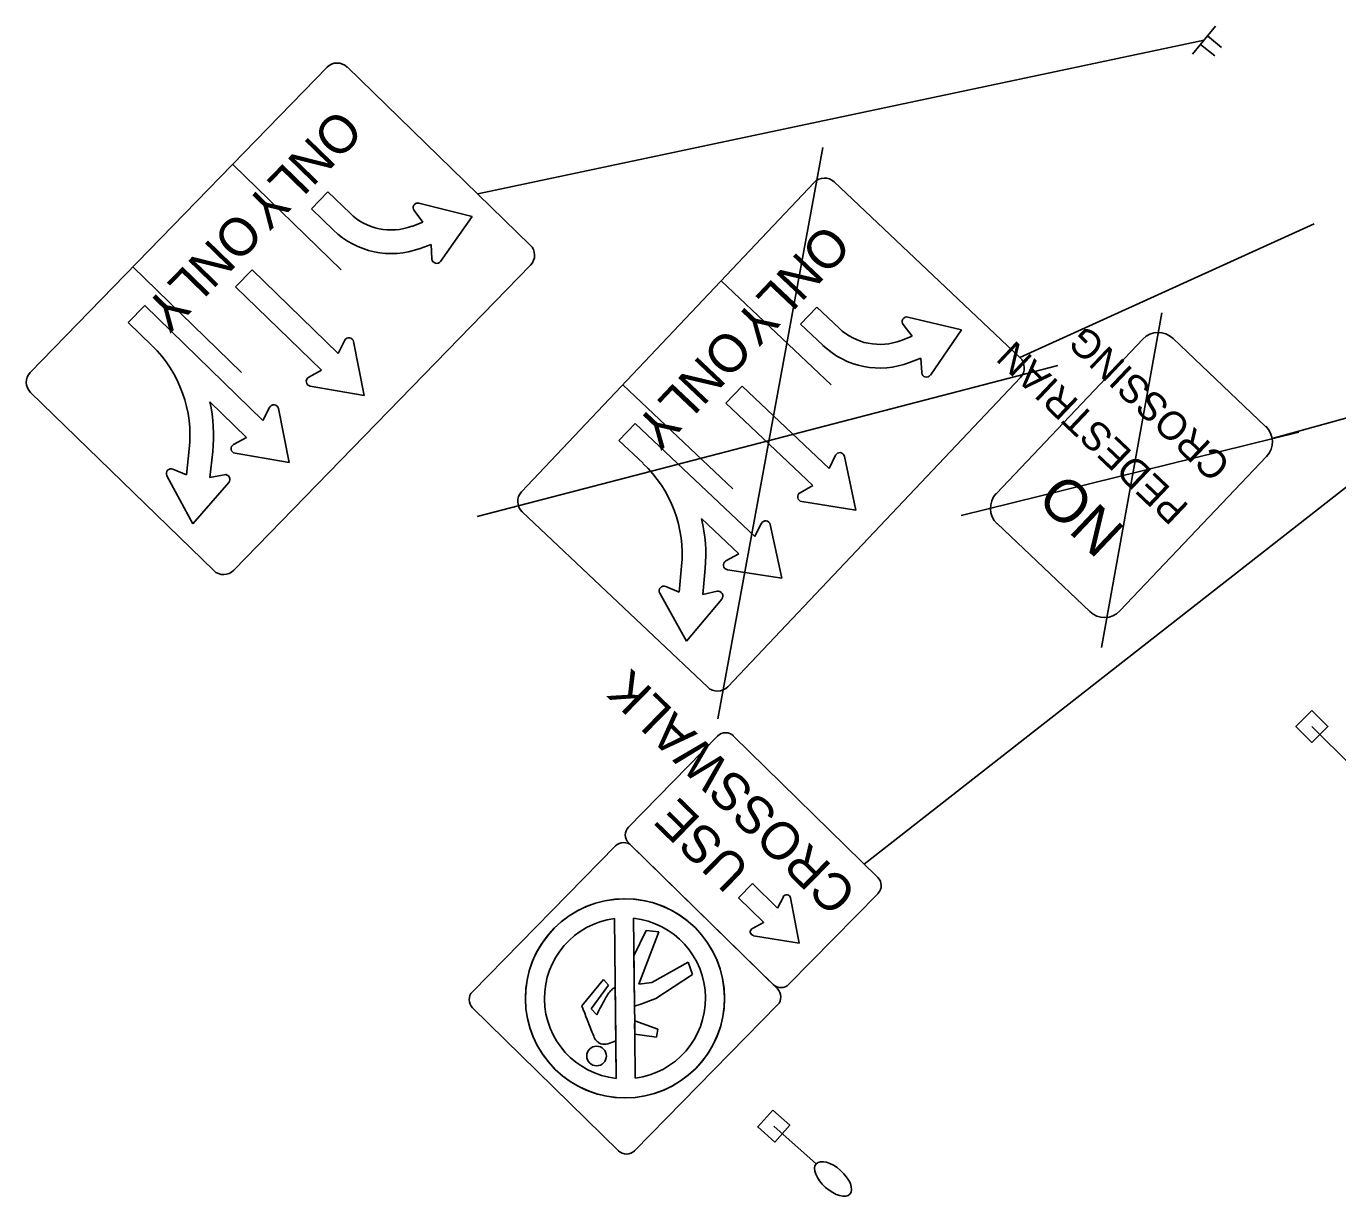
# Model space of a CAD drawing. Extents: x 1481212 to 1485683, y 378085 to 388655.
# Drawn here: x 1481273.4 to 1481389, y 378146.6 to 378249.9 of the extents above; entities that cross this region are included whole.
import ezdxf

# ---------------------------------------------------------------- set-up
doc = ezdxf.new("R2010")
doc.units = 0
for name, color, linetype in [('LT_X_Luminaires', 7, 'Continuous'), ('RW_X_CL_100_Curve_Data', 7, 'Continuous'), ('SC_Scratch15', 7, 'Continuous'), ('SC_Scratch8', 7, 'Continuous'), ('SN_P_Signs', 7, 'Continuous')]:
    doc.layers.add(name, color=color, linetype=linetype)

msp = doc.modelspace()

# ---------------------------------------------------------------- linework, layer by layer
at = {"layer": 'LT_X_Luminaires'}
for p, q in [((1481386.69, 378188.18), (1481390.23, 378184.64)), ((1481339.29, 378152.97), (1481343.02, 378149.64))]:
    msp.add_line(p, q, dxfattribs=at)
for points in [[(1481386.69, 378189.59), (1481388.1, 378188.18), (1481386.69, 378186.76), (1481385.27, 378188.18)], [(1481339.21, 378154.38), (1481340.7, 378153.05), (1481339.37, 378151.56), (1481337.88, 378152.89)]]:
    msp.add_lwpolyline(points, close=True, dxfattribs=at)
msp.add_ellipse((1481344.51, 378148.31), major_axis=(1.49, -1.33), ratio=0.5, dxfattribs=at)
at = {"layer": 'RW_X_CL_100_Curve_Data'}
for p, q in [((1481360.96, 378220.68), (1481386.88, 378232.45)), ((1481344.34, 378218.27), (1481334.65, 378227.43)), ((1481341.65, 378223.61), (1481343.08, 378225.12)), ((1481343.08, 378225.12), (1481345.04, 378223.26)), ((1481351.1, 378224.24), (1481355.81, 378223.12)), ((1481343.61, 378221.75), (1481341.65, 378223.61)), ((1481351.48, 378222.56), (1481350.68, 378223.57)), ((1481355.81, 378223.12), (1481353.08, 378219.13)), ((1481350.5, 378222.18), (1481351.48, 378222.56)), ((1481352.23, 378220.62), (1481351.25, 378220.24)), ((1481352.32, 378219.34), (1481352.23, 378220.62)), ((1481383.18, 378213.53), (1481401.74, 378218.69)), ((1481335.68, 378209.11), (1481325.99, 378218.27)), ((1481336.49, 378218.16), (1481335.06, 378216.64)), ((1481344.16, 378210.9), (1481336.49, 378218.16)), ((1481335.06, 378216.64), (1481342.73, 378209.39)), ((1481327.08, 378214.87), (1481325.65, 378213.36)), ((1481337.63, 378204.9), (1481327.08, 378214.87)), ((1481325.65, 378213.36), (1481327.77, 378211.36)), ((1481344.73, 378212.06), (1481344.16, 378210.9)), ((1481346.52, 378207.24), (1481345.51, 378211.96)), ((1481342.73, 378209.39), (1481341.61, 378208.76)), ((1481341.75, 378207.98), (1481346.52, 378207.24)), ((1481332.92, 378206.48), (1481336.2, 378203.38)), ((1481338.19, 378206.06), (1481337.63, 378204.9)), ((1481339.99, 378201.23), (1481338.97, 378205.96)), ((1481336.2, 378203.38), (1481335.07, 378202.76)), ((1481331.17, 378202.29), (1481330.96, 378200.01)), ((1481333.03, 378199.81), (1481333.25, 378202.09)), ((1481335.21, 378201.98), (1481339.99, 378201.23)), ((1481329.24, 378199.92), (1481331.59, 378195.69)), ((1481330.96, 378200.01), (1481329.77, 378200.5)), ((1481334.29, 378200.08), (1481333.03, 378199.81)), ((1481331.59, 378195.69), (1481334.7, 378199.4))]:
    msp.add_line(p, q, dxfattribs=at)
for points in [[(1481342.84, 378236.09), (1481317.08, 378208.85)], [(1481360.96, 378220.68), (1481344.61, 378236.14)], [(1481371.8, 378222.29), (1481358.89, 378208.69)], [(1481382.61, 378214.61), (1481374.45, 378222.36)], [(1481335.24, 378191.67), (1481361.01, 378218.92)], [(1481369.77, 378198.36), (1481382.68, 378211.96)], [(1481317.13, 378207.08), (1481333.48, 378191.62)], [(1481358.96, 378206.04), (1481367.12, 378198.29)]]:
    msp.add_lwpolyline(points, dxfattribs=at)
for centre, radius, start, end in [((1481343.75, 378235.23), 1.25, 46.6, 136.6), ((1481351.01, 378223.83), 0.417, 76.601, 218.4791), ((1481348.62, 378227.04), 5.21, 226.6, 291.1173), ((1481373.16, 378221), 1.88, 46.5, 136.5), ((1481348.62, 378227.04), 7.29, 226.6, 291.1173), ((1481360.1, 378219.77), 1.25, 316.6, 46.6), ((1481352.73, 378219.36), 0.417, 183.7555, 325.6336), ((1481381.32, 378213.25), 1.88, 316.5, 46.5), ((1481345.1, 378211.88), 0.417, 12.0837, 153.9618), ((1481320.18, 378203.33), 11.04, 354.5857, 46.6), ((1481317.99, 378207.99), 1.25, 136.6, 226.6), ((1481341.81, 378208.4), 0.417, 119.2382, 261.1163), ((1481360.25, 378207.4), 1.88, 136.5, 226.5), ((1481320.18, 378203.33), 13.12, 354.5857, 13.8745), ((1481338.57, 378205.87), 0.417, 12.0837, 153.9618), ((1481335.27, 378202.39), 0.417, 119.2382, 261.1163), ((1481329.61, 378200.12), 0.417, 67.2239, 209.102), ((1481334.38, 378199.67), 0.417, 320.0694, 101.9475), ((1481368.41, 378199.65), 1.88, 226.5, 316.5), ((1481334.33, 378192.53), 1.25, 226.6, 316.6)]:
    msp.add_arc(centre, radius, start, end, dxfattribs=at)
at = {"layer": 'SC_Scratch15'}
for p, q in [((1481347.25, 378176.05), (1481401.74, 378218.69)), ((1481337.41, 378174.33), (1481336.18, 378173.07)), ((1481336.18, 378173.07), (1481338.38, 378170.92)), ((1481340.13, 378173.16), (1481339.62, 378172.16)), ((1481341.51, 378169.08), (1481340.77, 378173.07)), ((1481325.4, 378157.17), (1481325.27, 378171.25)), ((1481339.08, 378171.46), (1481339.08, 378171.46)), ((1481328.05, 378170.21), (1481326.97, 378167.97)), ((1481328.05, 378170.21), (1481326.97, 378167.97)), ((1481327.4, 378165.47), (1481329.15, 378170.07)), ((1481327.4, 378165.47), (1481329.15, 378170.07)), ((1481329.15, 378170.07), (1481328.05, 378170.21)), ((1481329.15, 378170.07), (1481328.05, 378170.21)), ((1481338.39, 378170.91), (1481337.4, 378170.38)), ((1481338.38, 378170.92), (1481338.39, 378170.91)), ((1481337.51, 378169.74), (1481341.51, 378169.08)), ((1481326.97, 378167.97), (1481327.02, 378163.61)), ((1481331.76, 378167.4), (1481328.54, 378165.61)), ((1481331.76, 378167.4), (1481328.54, 378165.61)), ((1481332.14, 378166.32), (1481331.76, 378167.4)), ((1481332.14, 378166.32), (1481331.76, 378167.4)), ((1481324.3, 378165.87), (1481322.37, 378163.57)), ((1481324.3, 378165.87), (1481322.37, 378163.57)), ((1481323.21, 378163.31), (1481324.72, 378165.38)), ((1481323.21, 378163.31), (1481324.72, 378165.38)), ((1481324.72, 378165.38), (1481324.3, 378165.87)), ((1481324.72, 378165.38), (1481324.3, 378165.87)), ((1481328.54, 378165.61), (1481327.4, 378165.47)), ((1481328.54, 378165.61), (1481327.4, 378165.47)), ((1481328.9, 378164.2), (1481332.14, 378166.32)), ((1481328.9, 378164.2), (1481332.14, 378166.32)), ((1481325.37, 378160.63), (1481325.32, 378165.18)), ((1481327.57, 378163.7), (1481328.9, 378164.2)), ((1481327.57, 378163.7), (1481328.9, 378164.2)), ((1481322.37, 378163.57), (1481322.38, 378163.56)), ((1481322.37, 378163.57), (1481322.38, 378163.56)), ((1481323.71, 378162.78), (1481323.21, 378163.31)), ((1481323.71, 378162.78), (1481323.21, 378163.31)), ((1481327.02, 378163.53), (1481327.57, 378163.7)), ((1481327.02, 378163.53), (1481327.57, 378163.7)), ((1481327.02, 378163.61), (1481327.02, 378163.53)), ((1481329.08, 378161.5), (1481327.04, 378162.23)), ((1481329.08, 378161.5), (1481327.04, 378162.23)), ((1481327.04, 378162.23), (1481327.04, 378161.99)), ((1481327.05, 378161.06), (1481328.96, 378160.8)), ((1481327.05, 378161.06), (1481328.96, 378160.8)), ((1481328.96, 378160.8), (1481329.08, 378161.5)), ((1481328.96, 378160.8), (1481329.08, 378161.5)), ((1481325.37, 378160.48), (1481325.37, 378160.63))]:
    msp.add_line(p, q, dxfattribs=at)
for points in [[(1481326.49, 378179.31), (1481334.34, 378187.32)], [(1481335.74, 378187.33), (1481348.46, 378174.87)], [(1481325.34, 378177.65), (1481312.74, 378164.8)], [(1481339.22, 378165.45), (1481326.5, 378177.91)], [(1481339.61, 378165.07), (1481326.76, 378177.67)], [(1481339.61, 378172.17), (1481337.41, 378174.33)], [(1481348.47, 378173.47), (1481340.62, 378165.46)], [(1481325.26, 378171.25), (1481325.32, 378165.66), (1481325.32, 378165.66), (1481325.32, 378165.66), (1481325.37, 378160.63), (1481325.37, 378160.63)], [(1481327.04, 378161.99), (1481327.02, 378163.61), (1481326.96, 378168.85), (1481326.94, 378171.27)], [(1481312.76, 378163.38), (1481325.61, 378150.78)], [(1481327.03, 378150.8), (1481339.62, 378163.65)], [(1481327.09, 378157.18), (1481327.05, 378161.01), (1481327.03, 378161.99), (1481327.04, 378161.99)], [(1481327.04, 378161.99), (1481327.05, 378161.06), (1481327.05, 378161.06)], [(1481325.37, 378160.63), (1481325.4, 378157.17)], [(1481325.37, 378160.63), (1481325.37, 378160.63)]]:
    msp.add_lwpolyline(points, dxfattribs=at)
for centre, radius in [((1481326.18, 378164.22), 8.77), ((1481323.68, 378159.14), 0.864)]:
    msp.add_circle(centre, radius, dxfattribs=at)
for centre, radius, start, end in [((1481335.05, 378186.63), 0.989, 45.5759, 135.5759), ((1481327.2, 378178.62), 0.989, 135.5759, 225.5759), ((1481326.06, 378176.95), 1, 45.5759, 135.5759), ((1481347.76, 378174.16), 0.989, 315.5759, 45.5759), ((1481340.43, 378173.01), 0.342, 10.4966, 153.2137), ((1481326.18, 378164.22), 8.77, 315.5759, 135.5759), ((1481326.18, 378164.22), 7.09, 97.395, 263.7472), ((1481326.18, 378164.22), 7.09, 97.395, 263.7472), ((1481326.18, 378164.22), 7.09, 277.4238, 83.8238), ((1481326.18, 378164.22), 7.09, 277.4238, 83.8238), ((1481326.18, 378164.22), 8.77, 135.5759, 315.5759), ((1481337.56, 378170.08), 0.342, 117.9381, 260.6551), ((1481339.92, 378166.15), 0.989, 225.5759, 315.5759), ((1481313.46, 378164.1), 1, 135.5759, 225.5759), ((1481338.91, 378164.35), 1, 315.5759, 45.5759), ((1481325.16, 378162.15), 1.54, 277.6511, 277.7042), ((1481326.31, 378151.5), 1, 225.5759, 315.5759)]:
    msp.add_arc(centre, radius, start, end, dxfattribs=at)
for points in [[(1481325.32, 378165.18), (1481325.25, 378165.16), (1481325.06, 378165.05), (1481324.76, 378164.7), (1481324.53, 378164.35), (1481324.17, 378163.69), (1481323.93, 378163.23), (1481323.71, 378162.78)], [(1481325.32, 378165.18), (1481325.25, 378165.16), (1481325.06, 378165.05), (1481324.76, 378164.7), (1481324.53, 378164.35), (1481324.17, 378163.69), (1481323.93, 378163.23), (1481323.71, 378162.78)], [(1481322.38, 378163.56), (1481322.74, 378162.66), (1481323.29, 378161.24), (1481323.49, 378160.72), (1481323.59, 378160.57), (1481323.71, 378160.46), (1481323.99, 378160.17), (1481324.69, 378160.16), (1481325.11, 378160.36), (1481325.37, 378160.48)], [(1481322.38, 378163.56), (1481322.74, 378162.66), (1481323.29, 378161.24), (1481323.49, 378160.72), (1481323.59, 378160.57), (1481323.71, 378160.46), (1481323.99, 378160.17), (1481324.69, 378160.16), (1481325.11, 378160.36), (1481325.37, 378160.48)]]:
    msp.add_open_spline(points, degree=3, dxfattribs=at)
at = {"layer": 'SC_Scratch8'}
for p, q in [((1481376.17, 378247.39), (1481378.2, 378249.86)), ((1481313.21, 378235.09), (1481377.19, 378248.62)), ((1481377.19, 378248.62), (1481377.19, 378248.62)), ((1481377.19, 378248.62), (1481377.19, 378248.62)), ((1481377.49, 378249), (1481378.73, 378247.98)), ((1481376.88, 378248.25), (1481378.12, 378247.24)), ((1481301.19, 378228.4), (1481291.63, 378237.69)), ((1481298.57, 378233.78), (1481300.02, 378235.27)), ((1481300.02, 378235.27), (1481301.97, 378233.38)), ((1481300.51, 378231.89), (1481298.57, 378233.78)), ((1481308.39, 378232.6), (1481307.61, 378233.62)), ((1481308.04, 378234.28), (1481312.73, 378233.09)), ((1481307.41, 378232.23), (1481308.39, 378232.6)), ((1481312.73, 378233.09), (1481309.94, 378229.14)), ((1481309.12, 378230.64), (1481308.13, 378230.28)), ((1481309.18, 378229.36), (1481309.12, 378230.64)), ((1481292.4, 378219.36), (1481282.84, 378228.66)), ((1481293.34, 378228.4), (1481291.89, 378226.91)), ((1481300.91, 378221.04), (1481293.34, 378228.4)), ((1481291.89, 378226.91), (1481299.46, 378219.55)), ((1481283.89, 378225.25), (1481282.43, 378223.75)), ((1481294.29, 378215.13), (1481283.89, 378225.25)), ((1481282.43, 378223.75), (1481284.52, 378221.72)), ((1481301.5, 378222.19), (1481300.91, 378221.04)), ((1481303.22, 378217.34), (1481302.28, 378222.08)), ((1481299.46, 378219.55), (1481298.33, 378218.93)), ((1481298.46, 378218.15), (1481303.22, 378217.34)), ((1481289.61, 378216.77), (1481292.84, 378213.63)), ((1481294.87, 378216.28), (1481294.29, 378215.13)), ((1481296.6, 378211.43), (1481295.66, 378216.17)), ((1481292.84, 378213.63), (1481291.71, 378213.02)), ((1481287.8, 378212.61), (1481287.55, 378210.33)), ((1481289.63, 378210.1), (1481289.87, 378212.38)), ((1481291.84, 378212.24), (1481296.6, 378211.43)), ((1481287.55, 378210.33), (1481286.37, 378210.84)), ((1481290.89, 378210.35), (1481289.63, 378210.1)), ((1481285.84, 378210.26), (1481288.13, 378206.01)), ((1481288.13, 378206.01), (1481291.29, 378209.67))]:
    msp.add_line(p, q, dxfattribs=at)
for points in [[(1481299.94, 378246.25), (1481273.8, 378219.36)], [(1481317.84, 378230.58), (1481301.71, 378246.27)], [(1481291.72, 378201.93), (1481317.87, 378228.82)], [(1481273.83, 378217.59), (1481289.96, 378201.91)]]:
    msp.add_lwpolyline(points, dxfattribs=at)
for centre, radius, start, end in [((1481300.84, 378245.37), 1.25, 45.8014, 135.8014), ((1481307.94, 378233.87), 0.417, 75.8024, 217.6805), ((1481305.6, 378237.12), 5.21, 225.8014, 290.3187), ((1481305.6, 378237.12), 7.29, 225.8014, 290.3187), ((1481316.97, 378229.69), 1.25, 315.8014, 45.8014), ((1481309.6, 378229.38), 0.417, 182.9568, 324.8349), ((1481301.87, 378222), 0.417, 11.2851, 153.1632), ((1481276.83, 378213.8), 11.04, 353.7871, 45.8014), ((1481274.7, 378218.49), 1.25, 135.8014, 225.8014), ((1481298.53, 378218.57), 0.417, 118.4395, 260.3176), ((1481276.83, 378213.8), 13.12, 353.7871, 13.0758), ((1481295.25, 378216.09), 0.417, 11.2851, 153.1632), ((1481291.91, 378212.65), 0.417, 118.4395, 260.3176), ((1481286.21, 378210.46), 0.417, 66.4252, 208.3033), ((1481290.97, 378209.94), 0.417, 319.2708, 101.1489), ((1481290.83, 378202.8), 1.25, 225.8014, 315.8014)]:
    msp.add_arc(centre, radius, start, end, dxfattribs=at)
at = {"layer": 'SN_P_Signs'}
for p, q in [((1481334.37, 378188.84), (1481343.62, 378239.17)), ((1481368.14, 378195.13), (1481373.46, 378224.61)), ((1481313.17, 378206.68), (1481364.31, 378219.98)), ((1481385.54, 378214.11), (1481355.79, 378206.76))]:
    msp.add_line(p, q, dxfattribs=at)

# ---------------------------------------------------------------- texts
at = {"layer": 'RW_X_CL_100_Curve_Data'}
for s, height, rotation, p in [('ONLY', 3.333, 226.6, (1481343.87, 378232.63)), ('CROSSING', 2.5, 136.5, (1481379.67, 378211.37)), ('ONLY', 3.333, 226.6, (1481335.21, 378223.47)), ('PEDESTRIAN', 2.5, 136.5, (1481375.96, 378207.58)), ('NO', 3.75, 136.5, (1481370.36, 378205.56))]:
    msp.add_text(s, height=height, rotation=rotation, dxfattribs=at).set_placement(p)
at = {"layer": 'SC_Scratch15'}
for s, p in [('CROSSWALK', (1481346.79, 378173.64)), ('USE', (1481337.35, 378175.7))]:
    msp.add_text(s, height=3.296, rotation=135.5759, dxfattribs=at).set_placement(p)
at = {"layer": 'SC_Scratch8'}
for p in [(1481300.92, 378242.76), (1481292.13, 378233.73)]:
    msp.add_text('ONLY', height=3.333, rotation=225.8014, dxfattribs=at).set_placement(p)

doc.saveas('drawing.dxf')
